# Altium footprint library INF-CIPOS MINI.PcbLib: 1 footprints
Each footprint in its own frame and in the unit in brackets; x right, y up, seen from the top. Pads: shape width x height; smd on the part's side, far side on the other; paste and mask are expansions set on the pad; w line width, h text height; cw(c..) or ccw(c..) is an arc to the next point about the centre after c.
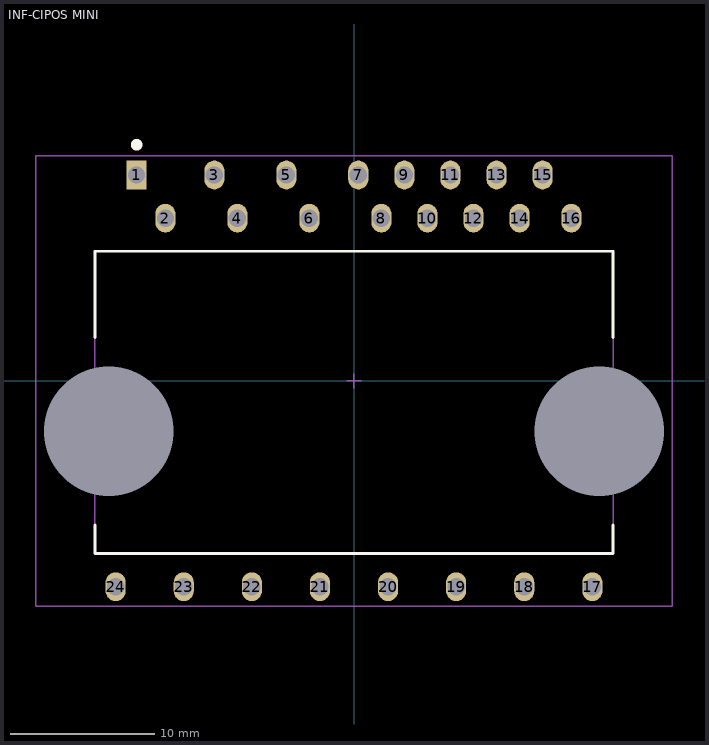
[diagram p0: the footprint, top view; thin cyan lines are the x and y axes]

## INF-CIPOS MINI [mm] "CIPOS MINI;24 pin, 21mm W X 36mm L X 5.6mm H body"
height 5.6
pads (26):
  rect 1.4x2 hole 1.2 paste+0 mask+0: 1(-15.1,14.3)
  oval 1.4x2 hole 1.2 paste+0 mask+0: 2(-13.1,11.3) 3(-9.7,14.3) 4(-8.1,11.3) 5(-4.7,14.3) 6(-3.1,11.3) 7(0.3,14.3) 8(1.9,11.3) 9(3.5,14.3) 10(5.1,11.3) 11(6.7,14.3) 12(8.3,11.3) 13(9.9,14.3) 14(11.5,11.3) 15(13.1,14.3) 16(15.1,11.3) 17(16.555,-14.3) 18(11.825,-14.3) 19(7.095,-14.3) 20(2.365,-14.3) 21(-2.365,-14.3) 22(-7.095,-14.3) 23(-11.825,-14.3) 24(-16.555,-14.3)
  round 0 hole 9 unplated paste+0 mask+0: ""(-17.025,-3.5) ""(17.025,-3.5)
Top Overlay:
  circle w0.4: c-15.1,16.4 r0.2
  lines w0.2: -18,-10 -18,-12 18,-12 18,-10 ; -18,3 -18,9 18,9 18,3
M3 (ASY_Text_Top):
  text ".DESIGNATOR" at 0,0 h1.2
M13 (CMP_Body_OTL_Top):
  lines w0.1: -18,-12 -18,9 18,9 18,-12 -18,-12
M15 (CMP_Courtyard_Top):
  lines w0.1: -0.5,0 0.5,0 ; 0,-0.5 0,0.5 ; -22.1,-15.65 22.1,-15.65 22.1,15.65 -22.1,15.65 -22.1,-15.65
3D body "MDIP-24-X1.stp": height 5.61, standoff -4.25, extent -18,-14.56 18,14.56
